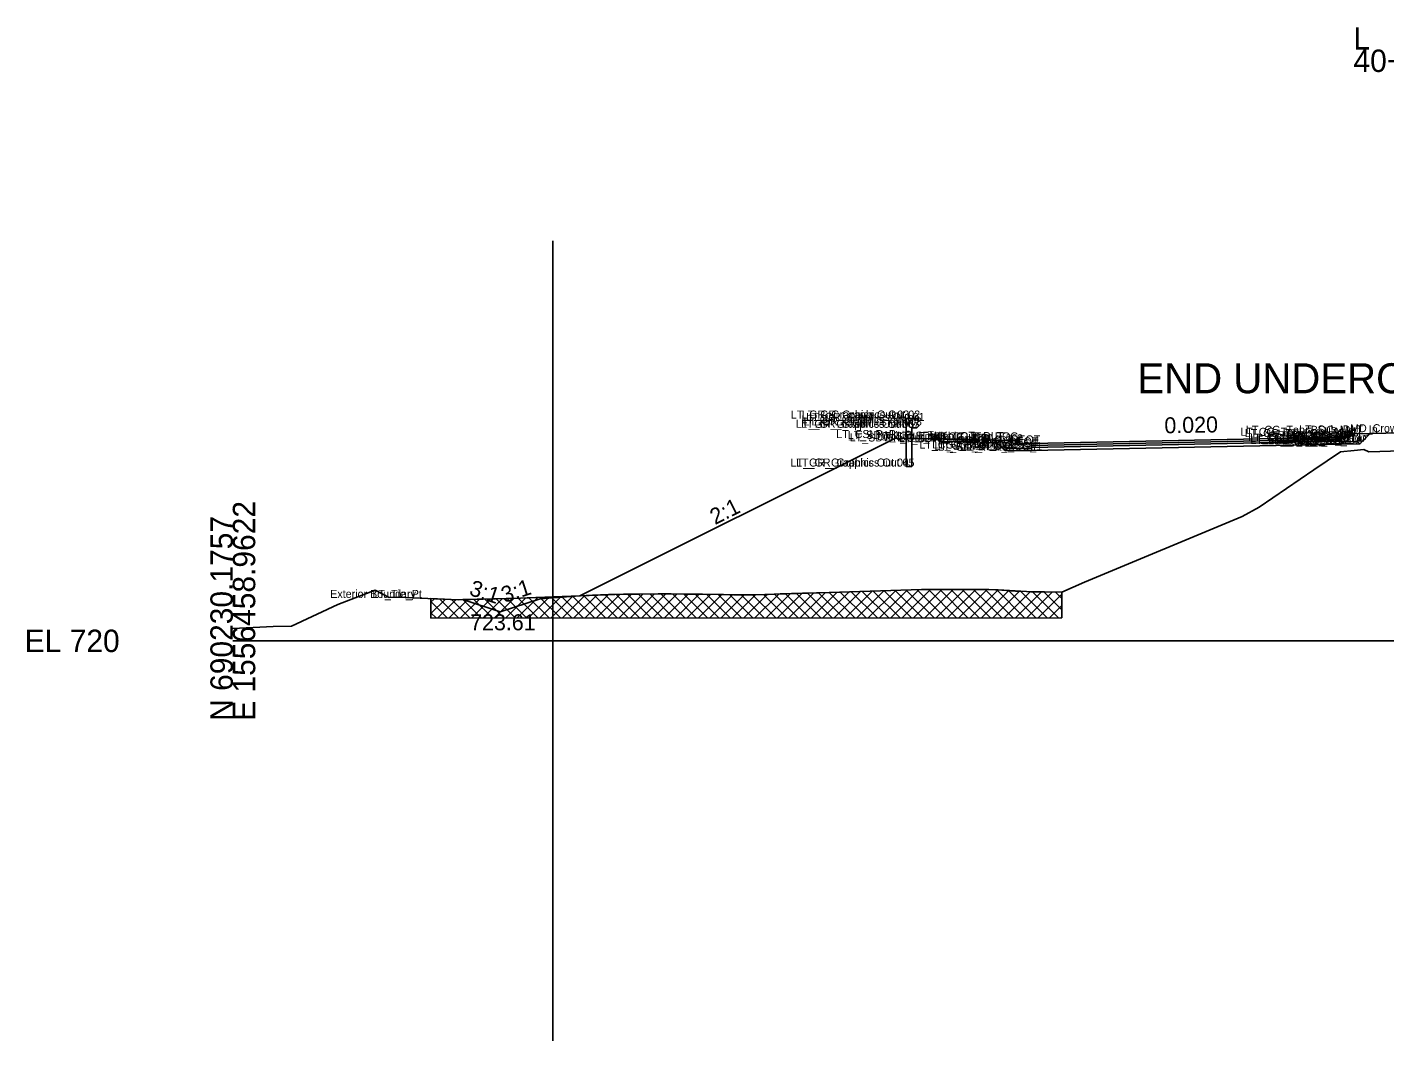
# Model space of a CAD drawing. Extents: x -26 to 6300, y -50 to 9577.
# Drawn here: x -25.7 to 143.9, y 6950 to 7076.7 of the extents above; entities that cross this region are included whole.
import ezdxf

# ---------------------------------------------------------------- set-up
doc = ezdxf.new("R2010")
doc.units = 0
for name, color, linetype in [('Default', 7, 'Continuous'), ('Exist Cross Section Cell', 7, 'Continuous'), ('Exist XS Ground Line', 7, 'Continuous'), ('Prop CMT Conc Surface', 7, 'Continuous'), ('Prop CMT Concrete Structures', 7, 'Continuous'), ('Prop CMT Guardrail Graphics', 7, 'Continuous'), ('Prop CMT Pvmt Course 1', 7, 'Continuous'), ('Prop CMT Pvmt Course 1 CG', 7, 'Continuous'), ('Prop CMT Pvmt Course 2', 7, 'Continuous'), ('Prop CMT Pvmt Course 3', 7, 'Continuous'), ('Prop CMT Pvmt Surface', 7, 'Continuous'), ('Prop CMT Slope Grass', 7, 'Continuous'), ('Prop CMT Subgrade Earthwork', 7, 'Continuous'), ('Prop XS DDE', 7, 'Continuous'), ('Prop XS DDE Text', 7, 'Continuous'), ('Prop XS Earthwork Shape', 7, 'Continuous'), ('Prop XS SE Text', 7, 'Continuous'), ('Prop XS Side Slope Text', 7, 'Continuous'), ('Prop XS Undercut Exc', 7, 'Continuous'), ('Prop XS Undercut Exc Hatch', 7, 'Continuous'), ('Prop XSC Text', 7, 'Continuous'), ('Scratch_Level_7', 7, 'Continuous')]:
    doc.layers.add(name, color=color, linetype=linetype)

msp = doc.modelspace()

# ---------------------------------------------------------------- linework, layer by layer
at = {"layer": 'Exist Cross Section Cell'}
msp.add_line((0, 7000), (150, 7000), dxfattribs=at)
at = {"layer": 'Exist XS Ground Line'}
msp.add_lwpolyline([(0, 7001.56), (5.05, 7001.79), (7.35, 7001.85), (13.1, 7004.53), (17.8, 7006.33), (19.53, 7005.43), (20.58, 7005.47), (28.15, 7005.14), (35.96, 7005.34), (47.71, 7005.81), (49.94, 7005.84), (53.63, 7005.87), (65.15, 7005.75), (73.22, 7006.02), (86.04, 7006.4), (93.24, 7006.43), (95.61, 7006.36), (99.17, 7006.15), (101.39, 7006.12), (103.55, 7006.1), (106.42, 7007.35), (126.09, 7015.56), (128.23, 7016.72), (135.03, 7021.37), (138.38, 7023.63), (140.08, 7023.79), (141.28, 7023.92), (141.93, 7023.62), (146.02, 7023.77)], dxfattribs=at)
at = {"layer": 'Prop CMT Conc Surface'}
for points in [[(138.5, 7025.45), (139.25, 7025.47), (139.25, 7025.63), (140.01, 7025.88)], [(93.24, 7025.15), (88.24, 7025.25)], [(97.79, 7024.56), (97.79, 7025.06), (97.29, 7025.06)], [(99.79, 7024.68), (97.79, 7024.56)]]:
    msp.add_lwpolyline(points, dxfattribs=at)
at = {"layer": 'Prop CMT Concrete Structures'}
for points in [[(138.5, 7025.45), (139.25, 7025.47), (139.25, 7025.63), (140.01, 7025.88)], [(138.5, 7024.87), (138.5, 7025.45)], [(140.01, 7025.88), (140.01, 7024.9)], [(88.24, 7024.92), (88.24, 7025.25)], [(88.24, 7025.25), (93.24, 7025.15)], [(93.24, 7024.82), (88.24, 7024.92)], [(93.24, 7025.15), (93.24, 7024.82)], [(99.79, 7024.68), (97.79, 7024.56), (97.79, 7025.06), (97.29, 7025.06)], [(97.29, 7025.06), (97.29, 7024.05), (99.79, 7024.1)], [(99.79, 7024.1), (99.79, 7024.68)], [(140.01, 7024.9), (138.5, 7024.87)]]:
    msp.add_lwpolyline(points, dxfattribs=at)
at = {"layer": 'Prop CMT Guardrail Graphics'}
for points in [[(84.14, 7021.79), (84.14, 7027.79)], [(84.14, 7027.79), (85.47, 7027.79), (85.75, 7027.5)], [(85.75, 7027.5), (85.47, 7027.21)], [(85.47, 7027.21), (85.75, 7026.92)], [(85.75, 7026.92), (85.47, 7026.63), (84.81, 7026.63)], [(84.81, 7026.63), (84.81, 7021.79)], [(84.81, 7021.79), (84.14, 7021.79)]]:
    msp.add_lwpolyline(points, dxfattribs=at)
at = {"layer": 'Prop CMT Pvmt Course 1'}
for points in [[(138.5, 7025.45), (99.79, 7024.68)], [(138.5, 7025.2), (138.5, 7025.45)], [(99.79, 7024.43), (138.5, 7025.2)], [(99.79, 7024.68), (99.79, 7024.43)], [(138.5, 7025.2), (138.5, 7025.2), (138.5, 7025.2)]]:
    msp.add_lwpolyline(points, dxfattribs=at)
at = {"layer": 'Prop CMT Pvmt Course 1 CG'}
for points in [[(99.79, 7024.1), (96.79, 7024.04), (96.49, 7023.74)], [(96.49, 7023.74), (99.79, 7023.8)], [(99.79, 7023.85), (99.79, 7024.1)], [(138.5, 7024.87), (140.51, 7024.91), (140.8, 7024.62)], [(138.5, 7024.62), (138.5, 7024.87)], [(140.76, 7024.62), (138.5, 7024.58)]]:
    msp.add_lwpolyline(points, dxfattribs=at)
at = {"layer": 'Prop CMT Pvmt Course 2'}
for points in [[(138.5, 7025.2), (99.79, 7024.43)], [(99.79, 7024.18), (138.5, 7024.95)], [(99.79, 7024.43), (99.79, 7024.18)], [(138.5, 7024.95), (138.5, 7025.2)]]:
    msp.add_lwpolyline(points, dxfattribs=at)
at = {"layer": 'Prop CMT Pvmt Course 3'}
for points in [[(138.5, 7024.95), (99.79, 7024.18)], [(99.79, 7023.8), (138.5, 7024.58)], [(99.79, 7024.18), (99.79, 7023.8)], [(138.5, 7024.58), (138.5, 7024.95)]]:
    msp.add_lwpolyline(points, dxfattribs=at)
at = {"layer": 'Prop CMT Pvmt Surface'}
msp.add_lwpolyline([(138.5, 7025.45), (99.79, 7024.68)], dxfattribs=at)
at = {"layer": 'Prop CMT Slope Grass'}
msp.add_line((82.79, 7025.35), (43.37, 7005.64), dxfattribs=at)
for points in [[(140.01, 7025.88), (150, 7026.08)], [(97.29, 7025.06), (82.79, 7025.35)]]:
    msp.add_lwpolyline(points, dxfattribs=at)
at = {"layer": 'Prop CMT Subgrade Earthwork'}
msp.add_line((96.49, 7023.74), (95.13, 7025.1), dxfattribs=at)
for points in [[(142.1, 7025.93), (140.8, 7024.62)], [(99.79, 7023.8), (96.49, 7023.74)], [(138.5, 7024.58), (99.79, 7023.8)], [(140.8, 7024.62), (138.5, 7024.58)], [(138.5, 7024.58), (138.5, 7024.58)]]:
    msp.add_lwpolyline(points, dxfattribs=at)
at = {"layer": 'Prop XS DDE'}
for p, q in [((38.39, 7005.27), (33.39, 7003.61)), ((43.37, 7005.64), (38.39, 7005.27))]:
    msp.add_line(p, q, dxfattribs=at)
msp.add_lwpolyline([(33.39, 7003.61), (28.75, 7005.16)], dxfattribs=at)
at = {"layer": 'Prop XS Earthwork Shape'}
msp.add_lwpolyline([(150, 7026.08), (142.1, 7025.93), (140.8, 7024.62), (138.5, 7024.58), (99.79, 7023.8), (96.49, 7023.74), (95.13, 7025.1), (93.24, 7025.14), (93.24, 7024.82), (88.24, 7024.92), (88.24, 7025.24), (82.79, 7025.35), (43.37, 7005.64), (47.71, 7005.81), (49.94, 7005.84), (53.63, 7005.87), (65.15, 7005.75), (73.22, 7006.02), (86.04, 7006.4), (93.24, 7006.43), (95.61, 7006.36), (99.17, 7006.15), (101.39, 7006.12), (103.55, 7006.1), (106.42, 7007.35), (126.09, 7015.56), (128.23, 7016.72), (135.03, 7021.37), (138.38, 7023.63), (140.08, 7023.79), (141.28, 7023.92), (141.93, 7023.62), (146.02, 7023.77)], dxfattribs=at)
at = {"layer": 'Prop XS Undercut Exc'}
for p, q in [((24.75, 7005.29), (24.75, 7002.82)), ((31.24, 7002.82), (33.7, 7005.29)), ((31.5, 7005.23), (33.91, 7002.83)), ((32.66, 7002.82), (35.16, 7005.32)), ((32.88, 7005.26), (35.32, 7002.83)), ((53.14, 7005.87), (50.82, 7005.85)), ((64.83, 7005.75), (62.56, 7005.77)), ((102.02, 7002.89), (103.55, 7004.42)), ((103.43, 7002.89), (103.55, 7003.01))]:
    msp.add_line(p, q, dxfattribs=at)
for points in [[(24.75, 7002.82), (103.55, 7002.89), (103.55, 7006.1)], [(44.94, 7005.7), (43.37, 7005.64), (36.78, 7005.38), (35.96, 7005.34), (28.75, 7005.16), (28.15, 7005.14), (24.75, 7005.29)], [(48.82, 7005.83), (46.92, 7005.78), (44.94, 7005.7)], [(50.82, 7005.85), (49.94, 7005.84), (48.82, 7005.83)], [(58.66, 7005.82), (56.56, 7005.84), (54.77, 7005.86), (53.14, 7005.87)], [(62.56, 7005.77), (60.77, 7005.79), (58.66, 7005.82)], [(66.88, 7005.8), (65.15, 7005.75), (64.83, 7005.75)], [(86.04, 7006.4), (79.63, 7006.21), (74.67, 7006.06), (71.18, 7005.95), (68.4, 7005.86), (66.88, 7005.8)], [(91.96, 7006.42), (89.05, 7006.41), (86.04, 7006.4)], [(97.78, 7006.23), (96.07, 7006.34), (94.43, 7006.4), (91.96, 7006.42)], [(103.55, 7006.1), (101.39, 7006.12), (101, 7006.13), (99.69, 7006.14), (99.17, 7006.15), (97.78, 7006.23)]]:
    msp.add_lwpolyline(points, dxfattribs=at)
at = {"layer": 'Prop XS Undercut Exc Hatch'}
for p, q in [((24.75, 7004.82), (25.2, 7005.27)), ((24.75, 7003.4), (26.56, 7005.21)), ((25.58, 7002.82), (27.91, 7005.15)), ((25.83, 7005.24), (28.25, 7002.82)), ((27, 7002.82), (29.35, 7005.17)), ((27.31, 7005.18), (29.67, 7002.82)), ((28.41, 7002.82), (30.8, 7005.21)), ((28.75, 7005.16), (31.08, 7002.82)), ((29.83, 7002.82), (32.25, 7005.25)), ((30.13, 7005.19), (32.49, 7002.82)), ((34.07, 7002.83), (36.62, 7005.37)), ((34.26, 7005.3), (36.73, 7002.83)), ((35.49, 7002.83), (38.09, 7005.43)), ((35.64, 7005.34), (38.14, 7002.83)), ((36.9, 7002.83), (39.56, 7005.49)), ((37, 7005.39), (39.56, 7002.83)), ((38.32, 7002.83), (41.04, 7005.55)), ((38.36, 7005.44), (40.97, 7002.83)), ((39.72, 7005.5), (42.38, 7002.83)), ((39.74, 7002.83), (42.51, 7005.61)), ((41.08, 7005.55), (43.8, 7002.84)), ((41.15, 7002.83), (43.98, 7005.67)), ((42.44, 7005.6), (45.21, 7002.84)), ((42.57, 7002.83), (45.46, 7005.72)), ((43.8, 7005.66), (46.62, 7002.84)), ((43.98, 7002.84), (46.93, 7005.78)), ((45.16, 7005.71), (48.04, 7002.84)), ((45.4, 7002.84), (48.38, 7005.82)), ((46.52, 7005.77), (49.45, 7002.84)), ((46.81, 7002.84), (49.81, 7005.84)), ((47.9, 7005.81), (50.86, 7002.84)), ((48.23, 7002.84), (51.24, 7005.85)), ((49.29, 7005.83), (52.27, 7002.84)), ((49.64, 7002.84), (52.67, 7005.86)), ((50.69, 7005.85), (53.69, 7002.84)), ((51.06, 7002.84), (54.08, 7005.86)), ((52.09, 7005.86), (55.1, 7002.85)), ((52.48, 7002.84), (55.48, 7005.85)), ((53.49, 7005.87), (56.51, 7002.85)), ((53.89, 7002.84), (56.88, 7005.84)), ((54.92, 7005.86), (57.93, 7002.85)), ((55.31, 7002.85), (58.28, 7005.82)), ((56.35, 7005.84), (59.34, 7002.85)), ((56.72, 7002.85), (59.68, 7005.81)), ((57.78, 7005.83), (60.75, 7002.85)), ((58.14, 7002.85), (61.08, 7005.79)), ((59.21, 7005.81), (62.16, 7002.85)), ((59.55, 7002.85), (62.48, 7005.78)), ((60.64, 7005.8), (63.58, 7002.85)), ((60.97, 7002.85), (63.88, 7005.76)), ((62.07, 7005.78), (64.99, 7002.85)), ((62.38, 7002.85), (65.28, 7005.75)), ((63.5, 7005.76), (66.4, 7002.86)), ((63.8, 7002.85), (66.75, 7005.8)), ((64.92, 7005.75), (67.82, 7002.86)), ((65.22, 7002.86), (68.21, 7005.85)), ((66.3, 7005.78), (69.23, 7002.86)), ((66.63, 7002.86), (69.67, 7005.9)), ((67.67, 7005.83), (70.64, 7002.86)), ((68.05, 7002.86), (71.14, 7005.95)), ((69.04, 7005.88), (72.05, 7002.86)), ((69.46, 7002.86), (72.6, 7006)), ((70.41, 7005.92), (73.47, 7002.86)), ((70.88, 7002.86), (74.06, 7006.04)), ((71.78, 7005.97), (74.88, 7002.86)), ((72.29, 7002.86), (75.52, 7006.09)), ((73.15, 7006.01), (76.29, 7002.87)), ((73.71, 7002.86), (76.98, 7006.13)), ((74.52, 7006.06), (77.71, 7002.87)), ((75.12, 7002.86), (78.43, 7006.17)), ((75.89, 7006.1), (79.12, 7002.87)), ((76.54, 7002.87), (79.89, 7006.22)), ((77.26, 7006.14), (80.53, 7002.87)), ((77.96, 7002.87), (81.35, 7006.26)), ((78.64, 7006.18), (81.94, 7002.87)), ((79.37, 7002.87), (82.81, 7006.3)), ((80.01, 7006.22), (83.36, 7002.87)), ((80.79, 7002.87), (84.26, 7006.35)), ((81.38, 7006.26), (84.77, 7002.87)), ((82.2, 7002.87), (85.72, 7006.39)), ((82.76, 7006.3), (86.18, 7002.87)), ((83.62, 7002.87), (87.15, 7006.4)), ((84.13, 7006.34), (87.6, 7002.88)), ((85.03, 7002.87), (88.57, 7006.41)), ((85.5, 7006.38), (89.01, 7002.88)), ((86.45, 7002.87), (89.99, 7006.42)), ((86.9, 7006.4), (90.42, 7002.88)), ((87.86, 7002.88), (91.41, 7006.42)), ((88.31, 7006.41), (91.84, 7002.88)), ((89.28, 7002.88), (92.82, 7006.41)), ((89.71, 7006.41), (93.25, 7002.88)), ((90.69, 7002.88), (94.22, 7006.4)), ((91.12, 7006.42), (94.66, 7002.88)), ((92.11, 7002.88), (95.59, 7006.35)), ((92.54, 7006.42), (96.07, 7002.88)), ((93.53, 7002.88), (96.93, 7006.29)), ((93.97, 7006.4), (97.49, 7002.89)), ((94.94, 7002.88), (98.26, 7006.2)), ((95.43, 7006.36), (98.9, 7002.89)), ((96.36, 7002.88), (99.62, 7006.14)), ((96.91, 7006.29), (100.31, 7002.89)), ((97.77, 7002.89), (101.01, 7006.13)), ((98.42, 7006.2), (101.73, 7002.89)), ((99.19, 7002.89), (102.41, 7006.11)), ((99.89, 7006.14), (103.14, 7002.89)), ((100.6, 7002.89), (103.55, 7005.84)), ((101.32, 7006.12), (103.55, 7003.89)), ((102.75, 7006.11), (103.55, 7005.31)), ((24.75, 7004.91), (26.84, 7002.82)), ((24.75, 7003.5), (25.43, 7002.82))]:
    msp.add_line(p, q, dxfattribs=at)
at = {"layer": 'Scratch_Level_7'}
msp.add_line((40, 7050), (40, 6950), dxfattribs=at)

# ---------------------------------------------------------------- texts
at = {"layer": 'Default'}
for s, height, p in [('LT_GR_Graphics Out 03', 1, (69.71, 7027.79)), ('LT_GR_Graphics Out 02', 1, (71.08, 7027.79)), ('LT_GR_Graphics Out 06', 1, (70.35, 7026.63)), ('LT_GR_Graphics Out 07', 1, (70.99, 7026.63)), ('LT_GR_Graphics Out 09', 1, (71.03, 7027.21)), ('LT_GR_Graphics Out 08', 1, (71.29, 7026.92)), ('LT_GR_Graphics Out 01', 1, (71.64, 7027.5)), ('MD_Crown Point', 1, (139.58, 7026.08)), ('LT_CSLP_Pnt', 1, (75.39, 7025.35)), ('LT_SDWK_Out_Top', 1, (76.82, 7025.25)), ('LT_SDWK_Out_Bot', 1, (77.07, 7024.92)), ('LT_Sub_Trench_Out_DLT', 1, (80.51, 7025.1)), ('LT_SDWK_In_Top', 1, (82.98, 7025.15)), ('LT_SDWK_In_Bot', 1, (83.23, 7024.82)), ('LT_CG_Top_BOC', 1, (87.1, 7025.06)), ('LT_CG_Top_Face', 1, (87.63, 7025.06)), ('LT_CG_Top_Gut', 1, (88.16, 7024.56)), ('LT_PV2_OEOT', 1, (91.28, 7024.43)), ('LT_PV1_OEOT', 1, (91.52, 7024.68)), ('LT_CG_Top_Face_Med', 1, (125.87, 7025.63)), ('LT_CG_Top_Gut_Med', 1, (126.42, 7025.47)), ('LT_CG_Top_BOC_Med', 1, (126.57, 7025.88)), ('LT_CG_Bot_BOC_Med', 1, (126.85, 7024.9)), ('LT_CG_Bot_IE_Med', 1, (127.09, 7024.87)), ('LT_Sub_IEOT_CG_1', 1, (127.13, 7024.62)), ('LT_PV2_OEEOP', 1, (129.29, 7025.2)), ('LT_PV3_OEEOP', 1, (129.29, 7024.95)), ('LT_Sub_OEEOP', 1, (129.33, 7024.58)), ('LT_PV2_IEEOP', 1, (130.05, 7025.2)), ('LT_Sub_IEEOP', 1, (130.09, 7024.58)), ('LT_CG1_Shelf_In', 1, (130.71, 7024.91)), ('LT_PV2_PGL', 1, (131.26, 7025.2)), ('LT_Sub_PGL', 1, (131.31, 7024.58)), ('LT_PV1_PGL', 1, (131.5, 7025.45)), ('LT_Sub_IEOP', 1, (133.05, 7024.67)), ('LT_Sub_DLT_In', 1, (133.22, 7025.93)), ('LT_CG1_Shelf_Out', 1, (85.77, 7024.04)), ('LT_CG_Bot_BOC', 1, (87.38, 7024.05)), ('LT_Sub_OEOT_CG_1', 1, (87.65, 7023.85)), ('LT_Sub_OEOP', 1, (88.06, 7023.78)), ('LT_PV3_OEOT', 1, (91.28, 7024.18)), ('LT_Sub_OEOT', 1, (91.33, 7023.8)), ('LT_CG_Bot_IE', 1, (91.63, 7024.1)), ('LT_GR_Graphics Out 04', 1, (69.68, 7021.79)), ('LT_GR_Graphics Out 05', 1, (70.37, 7021.79)), ('Exterior Boundary', 1, (12.17, 7005.37)), ('LT_Tie_Pt', 1, (17.45, 7005.37)), ('-', 0.0001, (0, 7000))]:
    msp.add_text(s, height=height, dxfattribs=at).set_placement(p)
at = {"layer": 'Exist Cross Section Cell'}
for s, p in [('L', (140, 7073.91)), ('40+50.00 / 1', (140, 7071.11)), ('EL 720', (-26, 6998.6))]:
    msp.add_text(s, height=2.8, dxfattribs=at).set_placement(p)
for s, p in [('E 1556458.9622', (2.8, 6990)), ('N 690230.1757', (0, 6990))]:
    msp.add_text(s, height=2.8, rotation=90, dxfattribs=at).set_placement(p)
at = {"layer": 'Prop XS DDE Text'}
for rotation, p in [(341.5651, (29.41, 7005.77)), (17.9773, (33.91, 7004.73))]:
    msp.add_text('3:1', height=2, rotation=rotation, dxfattribs=at).set_placement(p)
msp.add_text('723.61', height=2, dxfattribs=at).set_placement((29.65, 7001.32))
at = {"layer": 'Prop XS SE Text'}
msp.add_text('0.020', height=2, rotation=1.1458, dxfattribs=at).set_placement((116.4, 7025.93))
at = {"layer": 'Prop XS Side Slope Text'}
msp.add_text('2:1', height=2, rotation=26.5651, dxfattribs=at).set_placement((60.24, 7014.47))
at = {"layer": 'Prop XSC Text'}
msp.add_text('END UNDERCUT AT STA 40+75', height=3.75, dxfattribs=at).set_placement((113.01, 7030.95))

doc.saveas('drawing.dxf')
